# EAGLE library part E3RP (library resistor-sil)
SIL RESISTOR
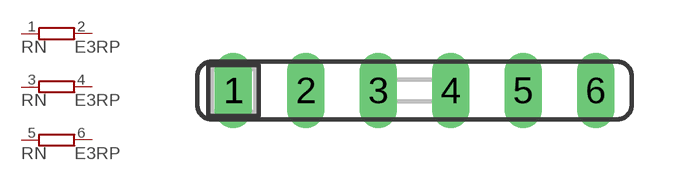
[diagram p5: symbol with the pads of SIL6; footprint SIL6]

Designator prefix RN; gates A=RPV B=RPV C=RPV

## E3RP (OC_FARNELL: unknown; OC_NEWARK: unknown)  [SIL6]
1  A:1  pas
2  A:2  pas
3  B:1  pas
4  B:2  pas
5  C:1  pas
6  C:2  pas

## Footprint SIL6 (pad centres in mm)
Single In Line
drill 0.813 long: 1 -6.35,0; 2 -3.81,0; 3 -1.27,0; 4 1.27,0; 5 3.81,0; 6 6.35,0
